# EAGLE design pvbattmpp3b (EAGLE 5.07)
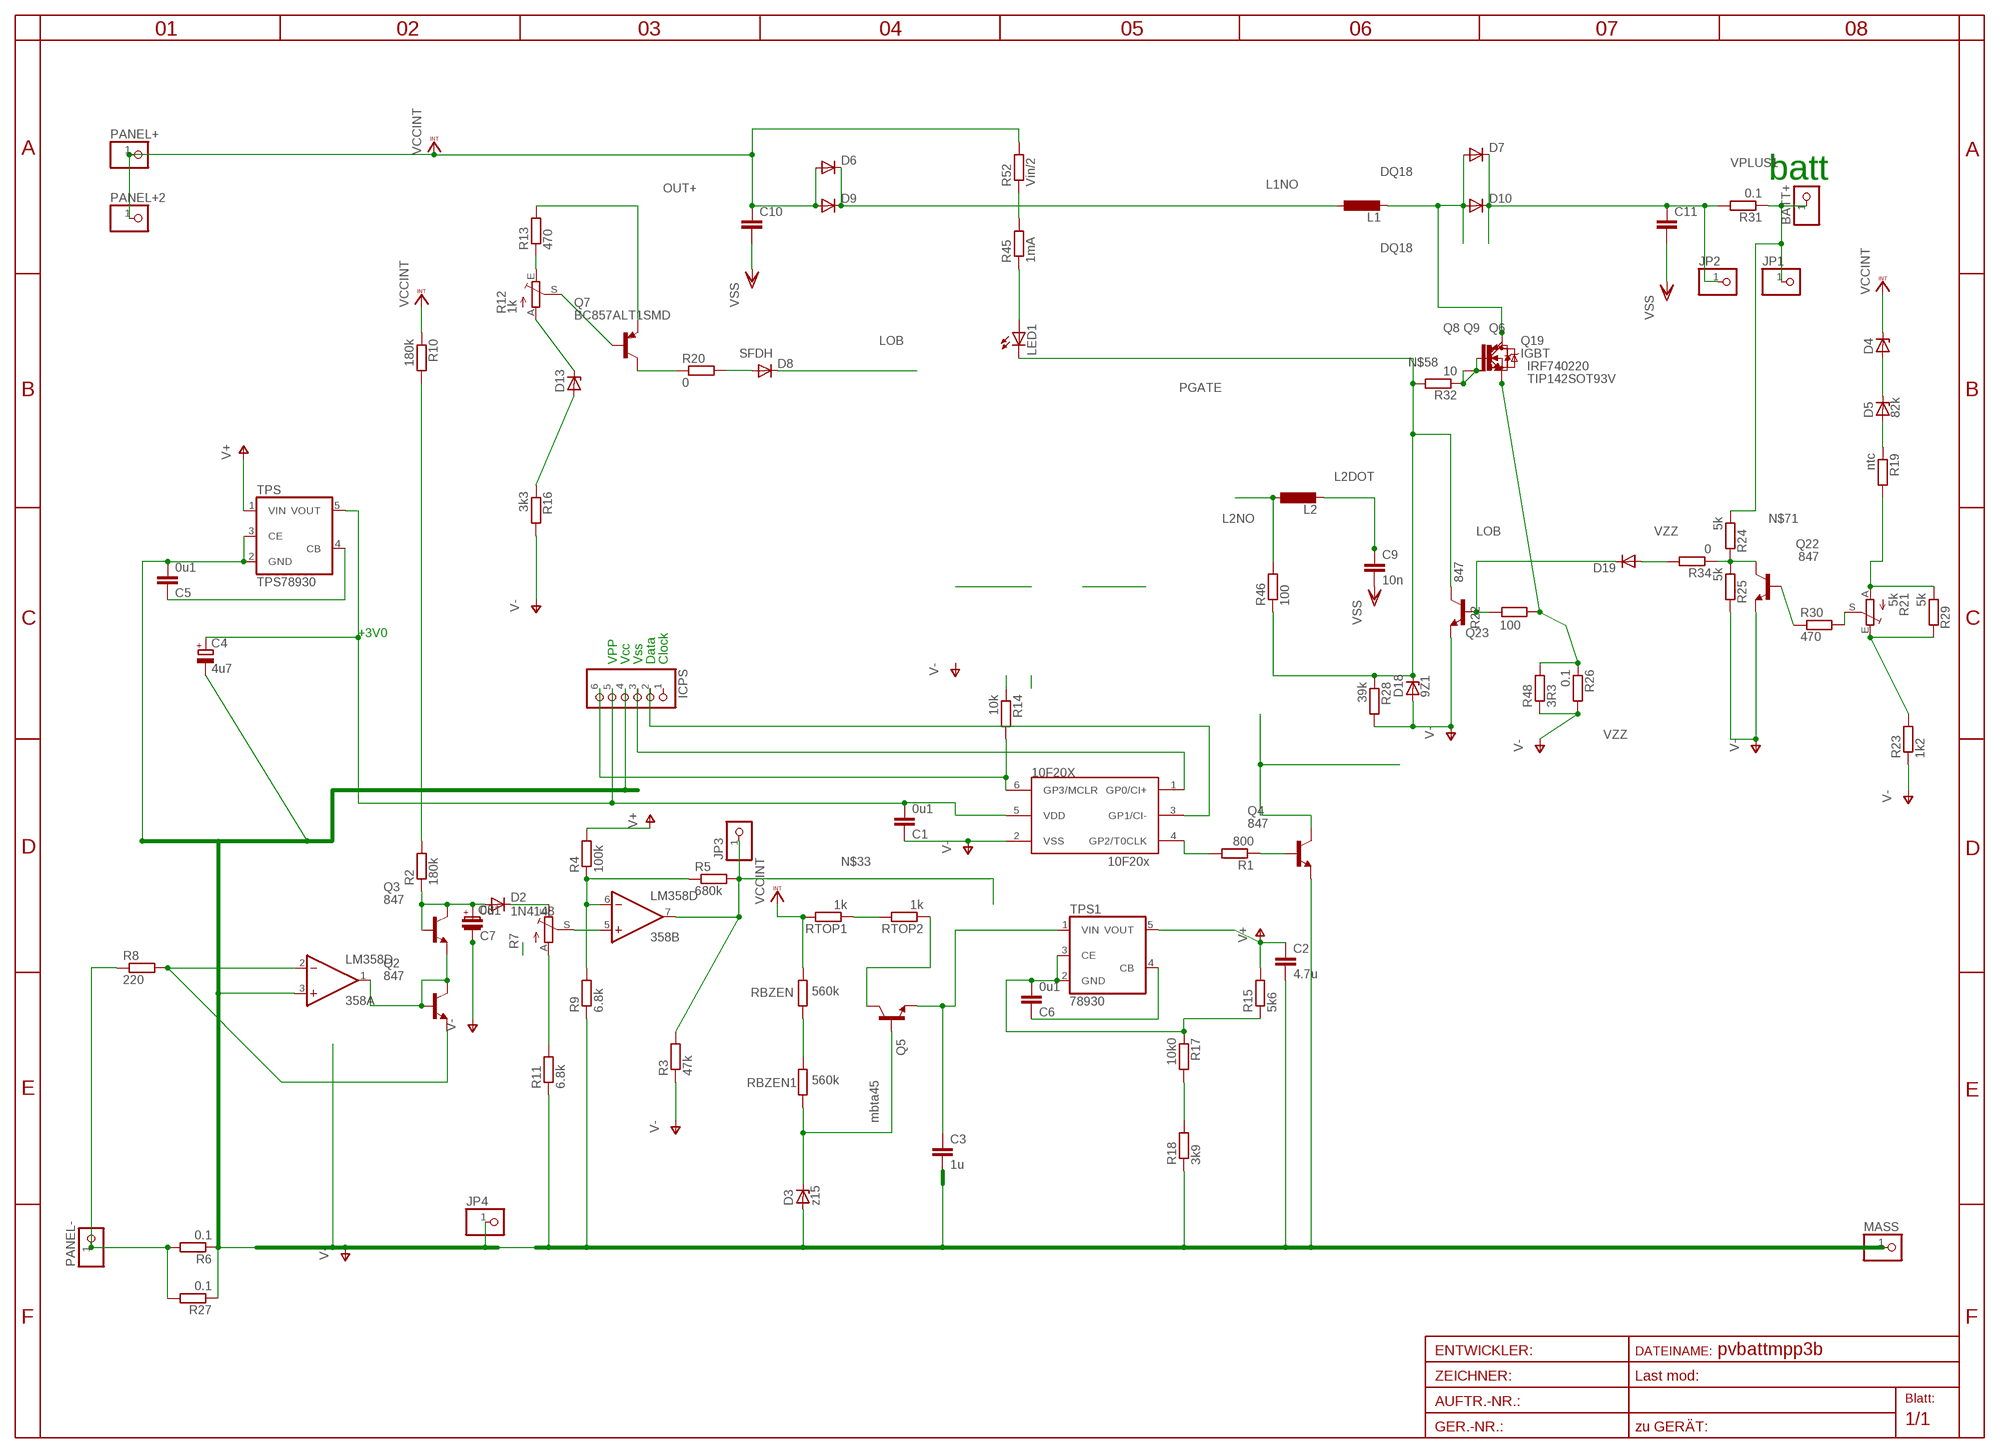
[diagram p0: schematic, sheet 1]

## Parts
10F20X  10F20x  PIC10F204OT  [SOT23-6]
358  LM358D  [SO08]
BATT+  PINHD-1X12MM3  [1X2MM3]
C1  0u1  C-EUC1206  [C1206]
C2  4.7u  C-EUC1206  [C1206]
C3  1u  C-EUC1206  [C1206]
C4  4u7  CPOL-EUSMCA  [SMC_A]
C5  0u1  C-EUC0805  [C0805]
C6  0u1  C-EUC0805  [C0805]
C7  0u1  C-EUC1608  [C1608]
C8  CPOL-EUSMCA  [SMC_A]
C9  10n  C-EUC0805  [C0805]
C10  C-EU075-052X106  [C075-052X106]
C11  C-EU075-052X106  [C075-052X106]
D2  1N4148  DIODE-SOD80C  [SOD80C]
D3  z15  ZENER-DIODESOD80C  [SOD80C]
D4  ZENER-DIODESOD80C  [SOD80C]
D5  82k  ZENER-DIODESOD80C  [SOD80C]
D6  DIODE-SMC  [SMC]
D7  DIODE-SMC  [SMC]
D8  DIODE-MINIMELF  [MINIMELF]
D9  DIODE-SMC  [SMC]
D10  DIODE-SMC  [SMC]
D13  ZENER-DIODESOD80C  [SOD80C]
D18  9Z1  ZENER-DIODESOD80C  [SOD80C]
D19  DIODE-MINIMELF  [MINIMELF]
ICPS  PINHD-1X6  [1X06BOX]
JP1  PINHD-1X11MM6  [1X1MM8]
JP2  PINHD-1X11MM6  [1X1MM8]
JP3  PINHD-1X11MM6  [1X1MM8]
JP4  PINHD-1X11MM6  [1X1MM8]
L1  L-EUOPEN6  [OPEN6_3]
L2  L-EUOPEN6  [OPEN6_3]
LED1  LEDCHIPLED_1206  [CHIPLED_1206]
MASS  PINHD-1X12MM3  [1X2MM3]
PANEL+  PINHD-1X11MM6  [1X1MM8]
PANEL+2  PINHD-1X12MM3  [1X2MM3]
PANEL-  PINHD-1X12MM3  [1X2MM3]
Q2  847  BC847ALT1SMD  [SOT23]
Q3  847  BC847ALT1SMD  [SOT23]
Q4  847  BC847ALT1SMD  [SOT23]
Q5  mbta45  BC847ALT1SMD  [SOT23]
Q6  IRF740220  [TO220BV]
Q7  BC857ALT1SMD  [SOT23-BEC]
Q8  IRG4BC15UD-S  [D2PACK]
Q9  TIP142SOT93V  [SOT93V]
Q19  IGBT  N-HEXFET_DPAK-  [TO252]
Q22  847  BC847ASMD  [SOT23]
Q23  847  BC847ASMD  [SOT23]
R1  800  R-EU_R0805  [R0805]
R2  180k  R-EU_0207/15  [0207/15]
R3  47k  R-EU_R0805  [R0805]
R4  100k  R-EU_R1206  [R1206]
R5  680k  R-EU_R0805  [R0805]
R6  0.1  R-EU_0207/10  [0207/10]
R7  TRIM_EU-S64W  [S64W]
R8  220  R-EU_R0805  [R0805]
R9  6.8k  R-EU_R1206  [R1206]
R10  180k  R-EU_R1206  [R1206]
R11  6.8k  R-EU_R0805  [R0805]
R12  1k  TRIM_EU-S64W  [S64W]
R13  470  R-EU_R0805  [R0805]
R14  10k  R-EU_R0805  [R0805]
R15  5k6  R-EU_R0805  [R0805]
R16  3k3  R-EU_R0805  [R0805]
R17  10k0  R-EU_R0805  [R0805]
R18  3k9  R-EU_R0805  [R0805]
R19  ntc  R-EU_0204/5  [0204/5]
R20  0  R-EU_R0805  [R0805]
R21  5k  TRIM_EU-S64W  [S64W]
R22  100  R-EU_R1206  [R1206]
R23  1k2  R-EU_R0805  [R0805]
R24  5k  R-EU_R0805  [R0805]
R25  5k  R-EU_R0805  [R0805]
R26  0.1  R-EU_R3216  [R3216]
R27  0.1  R-EU_R3216  [R3216]
R28  39k  R-EU_R0805  [R0805]
R29  5k  R-EU_R0805  [R0805]
R30  470  R-EU_R0805  [R0805]
R31  0.1  R-EU_R1210  [R1210]
R32  10  R-EU_R0805  [R0805]
R34  0  R-EU_R0805  [R0805]
R45  1mA  R-EU_R0805  [R0805]
R46  100  R-EU_R0805  [R0805]
R48  3R3  R-EU_0207/10  [0207/10]
R52  Vin/2  R-EU_R1206  [R1206]
RBZEN  560k  R-EU_R1206  [R1206]
RBZEN1  560k  R-EU_R1206  [R1206]
RTOP1  1k  R-EU_R1206  [R1206]
RTOP2  1k  R-EU_R1206  [R1206]
TPS  TPS78930  TPS78930SOT23-5  [SOT25]
TPS1  78930  TPS78930SOT23-5  [SOT25]

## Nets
CB: D3.C Q5.1(B) RBZEN1.2
DQ18: D7.A D10.A L1.2 Q6.D Q8.2(C) Q9.C Q19.3(D)
FB: 358.2(A:-IN) Q2.2(E) R8.2
GND1: C6.1 TPS1.4(CB)
IN-: PANEL-.1 R6.2 R8.1 R27.2
L1NO: D6.C D9.C L1.1
L2DOT: C9.1 L2.2
L2NO: L2.1 R46.2
LOB: D8.C D19.C Q4.3(C) Q23.1(B) R22.2
N$1: Q4.1(B) R1.1
N$2: R7.A R11.2
N$4: 10F20X.1(GP0/CI+) ICPS.3
N$5: 10F20X.4(GP2/T0CLK) R1.2
N$6: R2.2 R10.2
N$7: 358.1(A:OUT) Q2.1(B) Q2.3(C) Q3.2(E)
N$8: 10F20X.3(GP1/CI-) ICPS.2
N$9: 10F20X.5(VDD) C1.2 C4.+ ICPS.5 TPS.5(VOUT)
N$10: Q22.1(B) R30.1
N$11: C5.1 TPS.4(CB)
N$12: C7.2 C8.+ D2.A Q3.1(B) Q3.3(C) R2.1
N$13: D2.C R7.E
N$15: 358.5(B:+IN) R7.S
N$16: Q5.3(C) RTOP2.1
N$17: 358.6(B:-IN) R4.1 R5.1 R9.2
N$18: D13.A R16.1
N$19: RBZEN1.1 RBZEN.2
N$20: R14.1
N$22: D5.A R19.1
N$26: Q7.B R12.S
N$27: LED1.A R45.1
N$28: R17.2 R18.2
N$29: RTOP1.1 RTOP2.2
N$30: D4.A D5.C
N$32: R19.2 R21.A R29.1
N$33: 358.7(B:OUT) JP3.1 R3.2 R5.2
N$34: R21.E R23.2 R29.2
N$35: R45.2 R52.1
N$37: R12.E R13.1
N$38: D13.C R12.A
N$58: Q6.G Q8.1(G) Q9.B Q19.1(G) R32.1
N$71: Q22.3(C) R24.2 R25.1 R34.1
OUT+: BATT+.1 JP1.1 Q7.E R13.2 R24.1 R31.1
PGATE: D18.C LED1.C Q23.3(C) R28.1 R32.2 R46.1
PIR: 10F20X.6(GP3/MCLR) ICPS.6 R14.2
PRB1: R21.S R30.2
SDFGKSD: Q7.C R20.1
SFDH: D8.A R20.2
SFET1: Q6.S Q8.3(E) Q9.E Q19.2(S) R22.1 R26.1 R48.2
V15: C3.1 Q5.2(E) TPS1.1(VIN)
V+: C2.1 R4.2 R15.2 TPS1.5(VOUT) TPS.1(VIN)
V-: 10F20X.2(VSS) 358.3(A:+IN) C1.1 C2.2 C3.2 C4.- C5.2 C7.1 C8.- C9.2 C10.2 C11.2 D3.A D18.A ICPS.4 JP4.1 MASS.1 Q4.2(E) Q22.2(E) Q23.2(E) R3.1 R6.1 R9.1 R11.1 R16.2 R18.1 R23.1 R25.2 R26.2 R27.1 R28.2 R48.1 TPS.2(GND) TPS.3(CE) ; supply symbol labelled VSS
VCCINT: C10.1 D4.C D6.A D9.A PANEL+2.1 PANEL+.1 R10.1 R52.2 RBZEN.1 RTOP1.2
VPLUS1: C11.1 D7.C D10.C JP2.1 R31.2
VZZ: D19.A R34.2
X: C6.2 R15.1 R17.1 TPS1.2(GND) TPS1.3(CE)
Unconnected: ICPS.1

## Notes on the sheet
- batt
- +3V0
- VPP | Vcc | Vss | Data | Clock

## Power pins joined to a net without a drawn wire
V+: 358.8(P:V+)
V-: 358.4(P:V-)

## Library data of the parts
10F20X = microchip-3:PIC10F2*: uPC nW 0,25/0,5k Program Flash memory Comparator
358 = linear:LM358: OP AMP also LM158; LM258; LM2904 Source: http://cache.national.com/ds/LM/LM158.pdf
BATT+ JP1-JP4 MASS PANEL+ PANEL+2 PANEL- = pinhead:PINHD-1X1: PIN HEADER
C1-C3 C5-C7 C9-C11 = rcl:C-EU: CAPACITOR, European symbol
C4 = rcl(2):CPOL-EU: POLARIZED CAPACITOR, European symbol
C8 = rcl:CPOL-EU: POLARIZED CAPACITOR, European symbol
D2 D6-D10 D19 = diode:DIODE-: DIODE
D3-D5 D13 D18 = diode:ZENER-DIODE: Z-Diode
ICPS = pinhead:PINHD-1X6: PIN HEADER
L1 L2 = rcl:L-EU: INDUCTOR, European symbol
LED1 = led:LED: LED
Q2-Q5 Q22 Q23 = transistor-npn:BC847*: NPN Transistor
Q6 = transistor-power:IRF740: N-CHANNEL MOS FET
Q7 = transistor-pnp:BC857*: PNP Transistror
Q8 = transistor-power:IRG4BC15UD-: INSULATED GATE BIPOLAR TRANSISTOR WITH ULTRAFAST SOFT RECOVERY DIODE
Q9 = transistor-power:TIP142: NPN DARLINGTON TRANSISTOR
Q19 = transistor-power:N-HEXFET_?-*: HEXFET® Power MOSFET
R1-R6 R8-R11 R13-R20 R22-R31 R34 RBZEN RBZEN1 RTOP1 RTOP2 = rcl:R-EU_: RESISTOR, European symbol
R7 R12 R21 = pot:TRIM_EU-: POTENTIOMETER
R32 R45 R46 R48 R52 = rcl-2:R-EU_: RESISTOR, European symbol
TPS TPS1 = v-reg:TPS78930

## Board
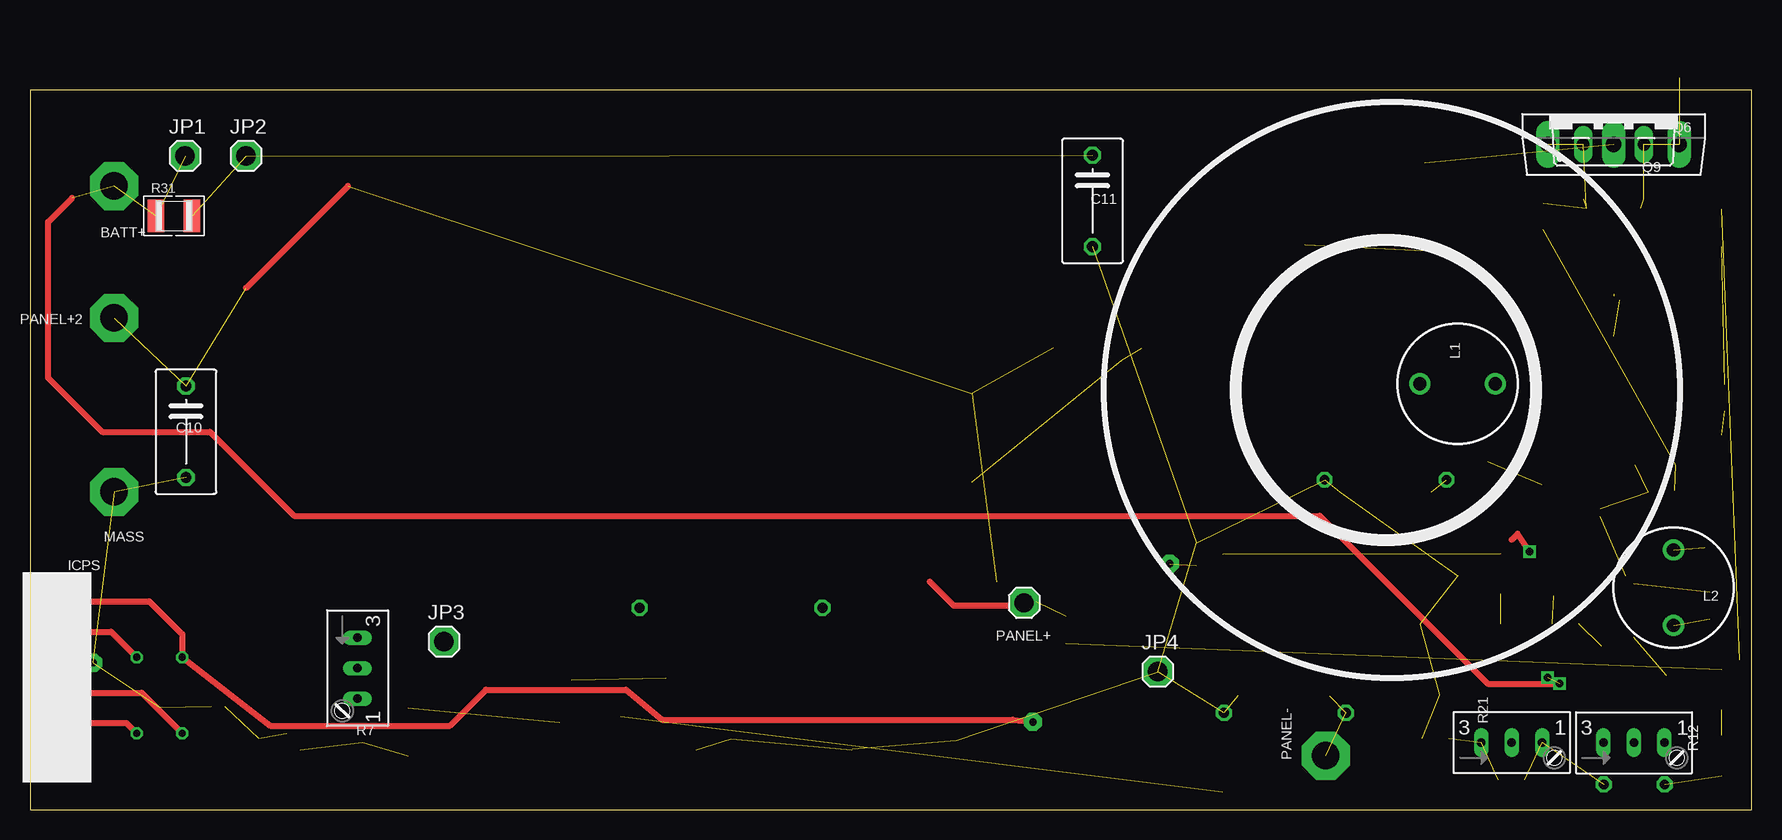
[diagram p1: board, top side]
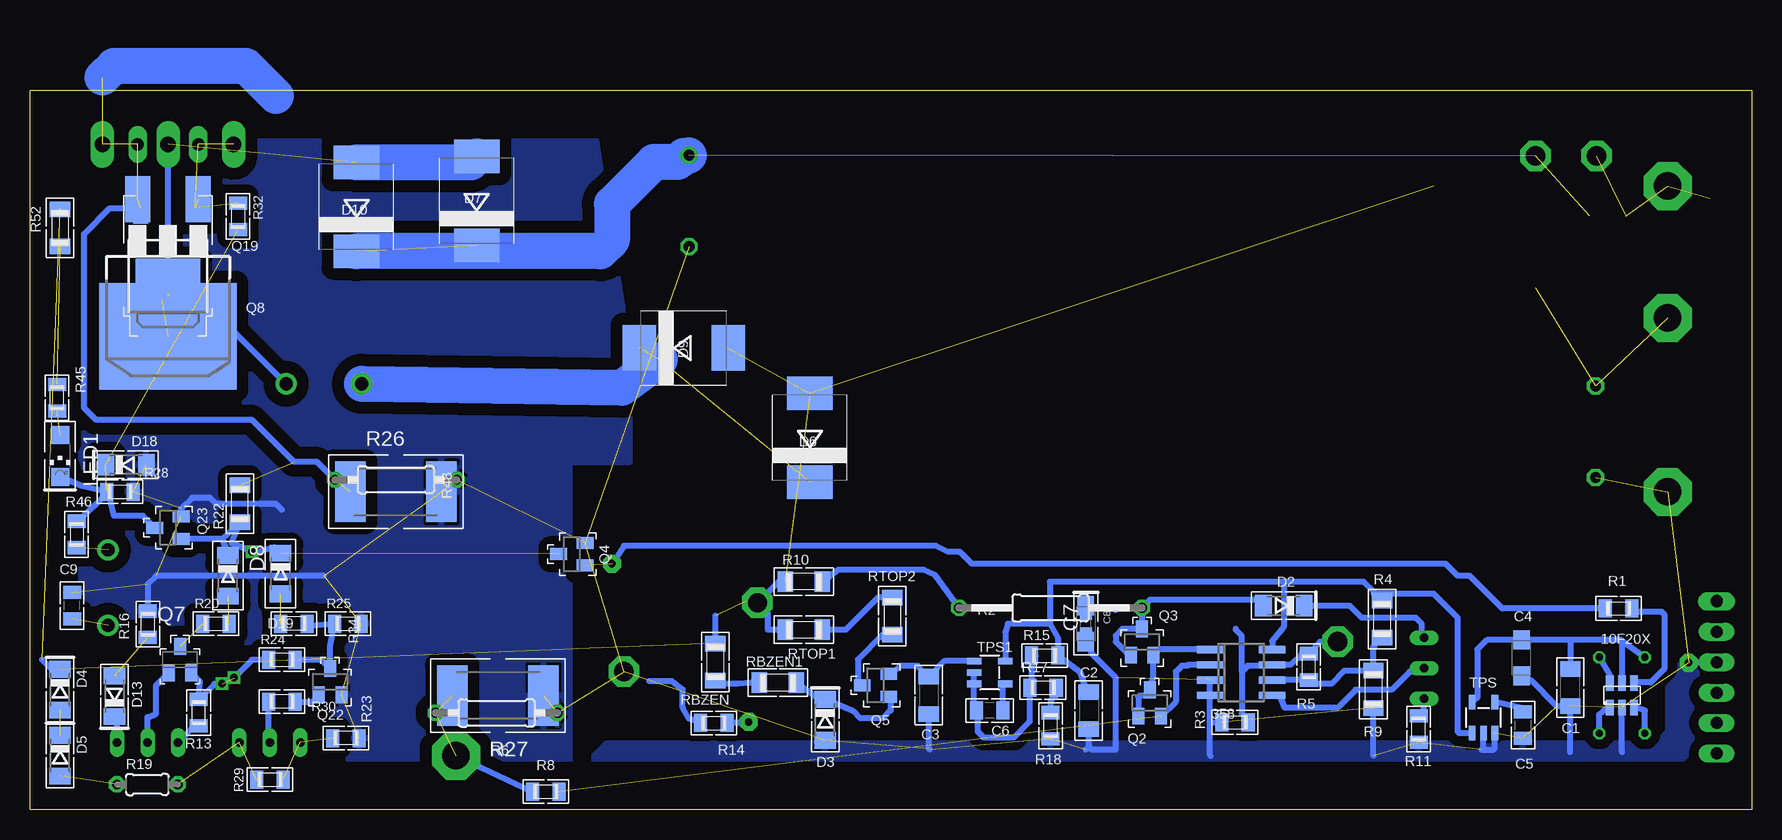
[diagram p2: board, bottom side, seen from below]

Size 143.5 x 60 mm. Coordinates in mm from the lower left corner, seen from the top.
Outline: 0,0 143.5,0 143.5,60 0,60 0,0
Copper layers (1*16): Top 0.035mm / dielectric 1.5mm / Bottom 0.035mm
Design rules "default *": minimum track width 10mil, minimum drill 24mil, track to track 8mil, track to pad 8mil, pad to pad 8mil, via to via 8mil, smd to smd 8mil, copper to edge 4mm, drill to drill 8mil, minimum pad ring 10mil, minimum via ring 8mil, stop-mask expansion 4mil, vias tented up to drill 0mil, thermal gap 10mil

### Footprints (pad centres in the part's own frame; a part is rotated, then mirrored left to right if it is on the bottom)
SOT23-6 = smd 0.635 x 1.27: 1 -1.016,-1.016; 2 0,-1.016; 3 1.016,-1.016; 4 1.016,1.016; 5 0,1.016; 6 -1.016,1.016
SO08 = smd 0.6 x 2.2: 1 -1.905,-2.6; 2 -0.635,-2.6; 3 0.635,-2.6; 4 1.905,-2.6; 5 1.905,2.6; 6 0.635,2.6; 7 -0.635,2.6; 8 -1.905,2.6
1X2MM3 = drill 2.3 pad 4 octagon: 1 0,0
C1206 = smd 1.3 x 1.7: 1 -1.55,0; 2 1.55,0
SMC_A = smd 1.6 x 1.4: + -1.5,0; - 1.5,0
C0805 = smd 1.1 x 1.5: 1 -1.1,0; 2 1.1,0
C1608 = smd 1.1 x 1: 1 -0.85,0; 2 0.85,0
C075-052X106 = drill 0.914 octagon: 1 -3.81,0; 2 3.81,0
SOD80C = smd 1.4 x 1.8: A 1.7,0; C -1.7,0
SMC = smd 2.8 x 3.8: A 3.7,0; C -3.7,0
MINIMELF = smd 1.4 x 1.8: A 1.7,0; C -1.7,0
1X06BOX = drill 1 long: 1 -6.35,0; 2 -3.81,0; 3 -1.27,0; 4 1.27,0; 5 3.81,0 | drill 1.016 long: 6 6.35,0
1X1MM8 = drill 1.6 pad 2.54 octagon: 1 0,0
OPEN6_3 = drill 1.1 pad 1.778 round: 1 -3.15,0; 2 3.15,0
CHIPLED_1206 = smd 1.5 x 1.5: A 0,-1.75; C 0,1.75
SOT23 = smd 1 x 1.4: 1 -0.95,-1.1; 2 0.95,-1.1; 3 0,1.1
TO220BV = drill 1.016 long: D 0,-2.54; G -2.54,-2.54; S 2.54,-2.54
SOT23-BEC = smd 1 x 1.4: B -0.95,-1.1; C 0,1.1; E 0.95,-1.1
D2PACK = smd 2.083 x 3.81: 1 -2.54,-8.89; 3 2.54,-8.89 | smd 11.43 x 8.89: 2 0,2.54
SOT93V = drill 1.3 pad 1.676 long: B -5.461,-2.54; C 0,-2.54; E 5.461,-2.54
TO252 = smd 1 x 1.6: 1 -2.28,-3.53 | smd 1.27 x 2.54: 2 2.28,-3.53 | smd 5.4 x 6.2: 3 0,3.77
R0805 = smd 1.1 x 1.5: 1 -1.1,0; 2 1.1,0
0207/15 = drill 0.813 octagon: 1 -7.62,0; 2 7.62,0
R1206 = smd 1.3 x 1.7: 1 -1.55,0; 2 1.55,0
0207/10 = drill 0.813 octagon: 1 -5.08,0; 2 5.08,0
S64W = drill 0.7 long: A 2.54,1.27; E -2.54,1.27; S 0,1.27
0204/5 = drill 0.813 octagon: 1 -2.54,0; 2 2.54,0
R3216 = smd 2.54 x 5.08: 1 -3.81,0; 2 3.81,0
R1210 = smd 1.4 x 2.7: 1 -1.5,0; 2 1.5,0
SOT25 = smd 0.55 x 1.2: 1 -0.95,-1.3; 2 0,-1.3; 3 0.95,-1.3; 4 0.95,1.3; 5 -0.95,1.3

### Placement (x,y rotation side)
10F20X  10.79,9.53 0 bottom
358  42.55,11.43 270 bottom
BATT+  7,52 0 top
C1  15.11,10.16 90 bottom
C2  55.24,8.26 270 bottom
C3  68.58,9.53 270 bottom
C4  19.18,12.63 270 bottom
C5  19.05,7.04 270 bottom
C6  63.5,8.26 180 bottom
C7  55.5,15.5 90 bottom
C8  55.5,15.5 270 bottom
C9  140,17 90 bottom
C10  13,31.5 270 top
C11  88.56,50.75 270 top
D2  39,17 180 bottom
D3  77.22,7.48 270 bottom
D4  141,10 270 bottom
D5  141,4.5 270 bottom
D6  78.5,31 90 bottom
D7  106.27,50.75 90 bottom
D8  127,19.5 270 bottom
D9  89,38.5 0 bottom
D10  116.29,50.25 90 bottom
D13  136.46,9.46 90 bottom
D18  135.5,28.75 0 bottom
D19  122.62,19.67 270 bottom
ICPS  2.9,11.02 90 top
JP1  12.92,54.5 0 top
JP2  18,54.5 0 top
JP3  34.5,14 0 top
JP4  94,11.5 0 top
L1  119,35.5 0 top
L2  137,18.5 270 top
LED1  141,29.5 180 bottom
MASS  7,26.5 0 top
PANEL+  82.86,17.24 0 top
PANEL+2  7,41 0 top
PANEL-  108,4.5 90 top
Q2  50.16,8.89 0 bottom
Q3  50.8,13.97 0 bottom
Q4  98.33,21.3 90 bottom
Q5  73.03,10.35 90 bottom
Q6  132,58 0 top
Q7  131,12.5 0 bottom
Q8  132,42 180 bottom
Q9  132,58 0 top
Q19  132,46.6 180 bottom
Q22  118.49,10.66 0 bottom
Q23  132,23.5 90 bottom
R1  11.08,16.77 0 bottom
R2  58.44,16.81 180 bottom
R3  43.05,7.27 0 bottom
R4  30.8,15.88 90 bottom
R5  36.9,11.9 90 bottom
R6  104.61,8.05 180 bottom
R7  26.04,11.79 270 top
R8  100.5,1.5 0 bottom
R9  31.52,10.03 90 bottom
R10  79,19 0 bottom
R11  27.75,6.71 90 bottom
R12  133.71,4.3 0 top
R13  129.44,8.08 90 bottom
R14  86.5,7.21 0 bottom
R15  58.92,12.84 0 bottom
R16  133.68,15.45 90 bottom
R17  59.05,10.16 0 bottom
R18  58.42,6.99 90 bottom
R19  133.72,2.09 0 bottom
R20  128,15.5 0 bottom
R21  123.51,4.32 0 top
R22  126,25.5 270 bottom
R23  117.16,5.96 180 bottom
R24  122.5,12.5 0 bottom
R25  117,15.5 0 bottom
R26  113,26.5 0 bottom
R27  104.5,9.5 180 bottom
R28  136,26.5 0 bottom
R29  123.5,2.5 0 bottom
R30  122.5,9 180 bottom
R31  12,49.5 0 top
R32  126.16,49.45 270 bottom
R34  121.5,15.5 180 bottom
R45  141.25,34.33 90 bottom
R46  139.61,22.94 270 bottom
R48  113,27.5 180 bottom
R52  141,48.5 90 bottom
RBZEN  86.36,12.29 270 bottom
RBZEN1  81.16,10.57 0 bottom
RTOP1  79,15 180 bottom
RTOP2  71.62,16.12 90 bottom
TPS  22.35,7.67 0 bottom
TPS1  63.5,11.43 270 bottom

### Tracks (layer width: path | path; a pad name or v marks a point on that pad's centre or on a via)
CB
  Bottom 0.5: Q5.1 71.75,9.23 71.75,8.26 72.39,7.62 74.3,7.62 74.85,8.18 D3.C 77.72,9.18 RBZEN1.2
DQ18  (3 unrouted)
  Bottom 0.5: Q9.C 132,43 132.5,42.5 129.15,42.5 L1.2
  Bottom 3: D10.A 106.77,53.95 D7.A
FB  (1 unrouted)
  Bottom 0.5: 358.2 46.94,12.06 47,12 47.5,12 48,11.5 48,9 Q2.2
GND1
  Bottom 0.5: C6.1 62.4,10.28 TPS1.4
IN-  (2 unrouted)
  Bottom 0.5: R8.1 PANEL-.1
L1NO  (2 unrouted)
  Bottom 3: L1.1 94.15,35.15 91,37.5
L2DOT  (1 unrouted)
L2NO  (1 unrouted)
LOB  (via drill 0.6)  (1 unrouted)
  Top 0.5: v125,21.5 124,23 123.5,22.5
  Bottom 0.5: 127.5,22.57 D8.C | 127.5,22.57 R22.2 126.71,22.21 v125,21.5 124.5,21.5 123.13,21.87 D19.C | Q23.1 127.52,22.55 127.5,22.57
N$1  (via drill 0.6 pad 1.5)  (1 unrouted)
  Bottom 0.5: R1.1 20.77,16.77 23.5,19.5 24.5,19.5 25.5,20.5 65,20.5 66,21.5 67,21.5 68,22 94,22 v95,20.5
N$2
  Bottom 0.5: R7.A 27.3,8.26 R11.2
N$4  (via drill 0.6)
  Top 0.5: ICPS.3 9.3,9.75 v12.7,6.35
  Bottom 0.5: v12.7,6.35 12.7,7.9 11.99,8.51 10F20X.1
N$5
  Bottom 0.5: 10F20X.4 9.72,10.6 8.4,10.6 7.24,11.76 7.24,16.24 7.5,16.5 9.71,16.5 R1.2
N$6
  Bottom 0.5: R2.2 68.06,19.56 69,20 76.14,20 R10.2
N$7
  Bottom 0.5: 358.1 49.38,13.34 Q3.2 49.9,12.42 49.9,10.9 50.16,10.34 Q2.3 50.66,9.5 51,9.5 51.12,9.38 Q2.1
N$8  (via drill 0.6)
  Top 0.5: ICPS.2 8.03,7.21 v8.89,6.35
  Bottom 0.5: v8.89,6.35 8.89,8.26 10F20X.3
N$9  (via drill 0.6)
  Top 0.5: ICPS.5 6.76,14.83 v8.89,12.7
  Bottom 0.5: 15.24,14.13 10.86,14.13 10.75,14.02 | 15.24,14.13 C4.+ 22.06,14.13 22.86,13.34 22.86,9.3 TPS.5 | v8.89,12.7 10.7,13.97 10.75,14.02 | 10F20X.5 10.79,13.97 10.75,14.02 | C1.2 15.11,14 15.24,14.13
N$10
  Bottom 0.5: R30.1 120,9 Q22.1
N$11
  Bottom 0.5: TPS.4 19.25,8.47 C5.1
N$12
  Bottom 0.5: D2.A 41,17.5 50.13,17.5 R2.1 | R2.1 52.82,16.78 53.12,16.73 | Q3.1 51.87,12.87 53,14 53,14.5 52.43,15.07 Q3.3 50.82,15.09 R2.1 | 53.12,16.73 53,16.62 | C7.2 C8.+ 55.23,16.73 53.12,16.73
N$13
  Bottom 0.5: D2.C 33.49,16.99 32.5,16 28,16 27.5,15.5 27.5,14.03 R7.E
N$15
  Bottom 0.5: 358.5 39.33,9.53 38.9,8.5 34.5,8.5 33,10 30,10 28.5,11.5 27.59,11.5 R7.S
N$16
  Bottom 0.5: RTOP2.1 72.43,14.57 74.5,12.5 74.5,10.73 Q5.3
N$17
  Bottom 0.5: R4.1 31.52,13.55 R9.2 33.92,11.57 35,10.5 36.59,10.5 R5.1 37.91,10.79 358.6
N$18  (1 unrouted)
N$19
  Bottom 0.5: RBZEN1.1 83.37,10.57 84.5,10.5 85.61,10.5 RBZEN.2
N$20
  Bottom 0.5: R14.1 88.59,7.59 89.1,8.5 89.1,10 90,10.7 91.87,10.7
N$22  (1 unrouted)
N$26
  Bottom 0.5: R12.S 133.71,7.71 133,8 133,10.35 Q7.B
N$27  (1 unrouted)
N$28
  Bottom 0.5: R18.2 58.42,9.08 58,9.5 58,10.12 R17.2
N$29
  Bottom 0.5: RTOP1.1 75.52,14.98 72.83,17.67 RTOP2.2
N$30  (1 unrouted)
N$32  (2 unrouted)
N$33
  Bottom 0.5: R3.2 42.05,7.54 42.5,8 42.5,11.5 | 42.5,11.5 42,12 40.01,12 358.7 38.44,12.06 37.5,13 R5.2 35.95,14 JP3.1 | 42.5,11.5 42.5,14.5 43,15 43,15.1
N$34  (2 unrouted)
N$35  (1 unrouted)
N$37
  Bottom 0.5: R13.1 129.76,6.98 R12.E
N$38
  Bottom 0.5: R12.A 136.25,7.04 D13.C
N$58  (4 unrouted)
N$71
  Bottom 0.5: R24.2 119.23,12.5 Q22.3 118.49,13.61 R25.1 120.1,15.3 R34.1
OUT+  (via drill 0.6)  (4 unrouted)
  Top 0.5: v127.5,10.5 121.5,10.5 107.5,24.5 22,24.5 15,31.5 6,31.5 1.5,36 1.5,49 3.5,51
  Bottom 0.5: R24.1 125,12.5 v126.5,11 | v127.5,10.5 128.12,10.5 R13.2 129.33,10.68 Q7.E
PGATE  (2 unrouted)
  Bottom 0.5: 137,26.5 136.5,24.5 134.1,24.5 Q23.3 | 137,26.5 137.1,26.6 R28.1 139.25,27 LED1.C | R46.1 139.46,24.04 137,26.5
PIR  (via drill 0.6, 0.6 pad 1.5)
  Top 0.5: v83.6,7.3 81.92,7.48 52.67,7.48 49.67,10 38,10 35,7 20.04,7 v12.7,12.7 12.7,14.61 9.94,17.37 ICPS.6
  Bottom 0.5: 10F20X.6 11.81,11.18 v12.7,12.7 | R14.2 84.58,7.21 v83.6,7.3
PRB1
  Bottom 0.5: R30.2 123.6,5.68 R21.S
SDFGKSD  (1 unrouted)
SFDH  (1 unrouted)
SFET1  (6 unrouted)
  Bottom 0.5: Q19.2 136.87,50.13 139,48 139,33.5 138,32.5 125,32.5 121.5,29 119.58,29 R48.2
  Bottom 3: 137.46,61.04 136.5,62 125.5,62 123,59.5
V15
  Bottom 0.5: TPS1.1 67.28,12.38 C3.1 69.5,12 71,12 71.7,11.3 Q5.2
V+
  Bottom 0.5: TPS.1 24.38,6.38 24.5,6.5 24.5,16 26.5,18 31.5,18 31.5,18.18 | 31.5,18.18 R4.2 | 39,19 32.32,19 31.5,18.18 | 39,19 58.5,19 58.5,15.5 | C2.1 55.24,9.74 55.5,10 56,11.5 R15.2 57.82,14.32 58.5,15.5 | TPS1.5 62.2,14.8 62,15.5 58.5,15.5 | 358.8 39.95,14.05 39,15.25 39,19
V-  (via drill 0.6 pad 1.5)  (28 unrouted)
  Top 0.5: ICPS.4 5.21,12.29 v5.25,12.25
  Bottom 0.5: 15.11,4.81 C1.1 16.23,8.62 18.41,10.79 18.84,10.79 C4.- | 10.79,4.81 10F20X.2 | 45.15,7.27 45.15,4.5 45.09,4.45 | 358.3 358.4 45.15,7.27 | v5.25,12.25 4.54,12.25 ICPS.4 | R9.1 31.52,4.53 31.5,4.5 | C3.2 68.58,5.08 68.5,5 | 55.24,5.25 C2.2 | 55.24,5.25 55.5,5 | TPS.3 21.4,5.1 21.5,5 22.5,5 22.35,5.15 TPS.2 | 55.24,5.25 54.99,5 53,5 53,11 55,13 C7.1 C8.- | 45.15,7.27 R3.1 | R16.2 133.68,18.82 133,19.5 119,19.5 | Q23.2 130.9,25.1 130,26 128.5,26 128,25.5 123,25.5 122.5,25
  pour Bottom (isolate 0.813): 1.5,12.5 6.5,12 7,11.5 7,6.5 8,5.5 95.5,5.5 96.5,4.5 96.5,3.5 95,2 8,2 5,5 5,9
  pour Bottom (isolate 1): 96.5,57 141.5,57 141.5,2.5 107,2.5 107,2 98.5,2 98.5,29 93.5,29 93.5,38
VCCINT  (8 unrouted)
  Top 0.5: 75,19 77,17 82.62,17 PANEL+.1 | 18,43.5 26.5,52
  Bottom 0.5: PANEL+.1 83.86,17.34 | RBZEN.1 86.36,16.16 | PANEL+.1 82,16.38 82,15 RTOP1.2 | PANEL+.1 81.1,19 R10.1 | D4.C 141.7,11.7 142.5,12.5
VPLUS1  (3 unrouted)
  Bottom 3: D10.C 95.95,46.55 95,47.5 95,50.5 91.5,54 89.5,54 89,54.5 88.62,54.5 C11.1
VZZ  (1 unrouted)
X
  Bottom 0.5: R15.1 59.66,12.84 60,12 60,11.01 R17.1 60.16,7.34 61.5,6 64,6 64.5,6.5 64.5,8.15 C6.2 64.8,8.46 TPS1.3 TPS1.2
